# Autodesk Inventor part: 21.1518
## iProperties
Created: 2006-12
Part Number: 21.1518
Material: Steel, Mild
Description: M6X12 C'SUNK SCREW
Document SubType Name: Modeling
Standard: DIN 7991
Designer: Andy Moles
Standards Organization: DIN
Language: en-US
Size Designation: M6x16
Categories: <MemberInstance Version="R10.0.0"><Categories><Category DisplayName="Fasteners" InternalName="e4da775c-781d-43d5-af7c-5136215cf5a6" Mnemonic="FSTN"><Category Di
Density: 7.86 g/cm^3
Mass: 3.46631 g
Surface Area: 4.65192 cm^2
Volume: 0.441007 cm^3
Author: Andy Moles
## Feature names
1. Revolution1
2. Extrusion1
3. Fillet1
4. Chamfer1
